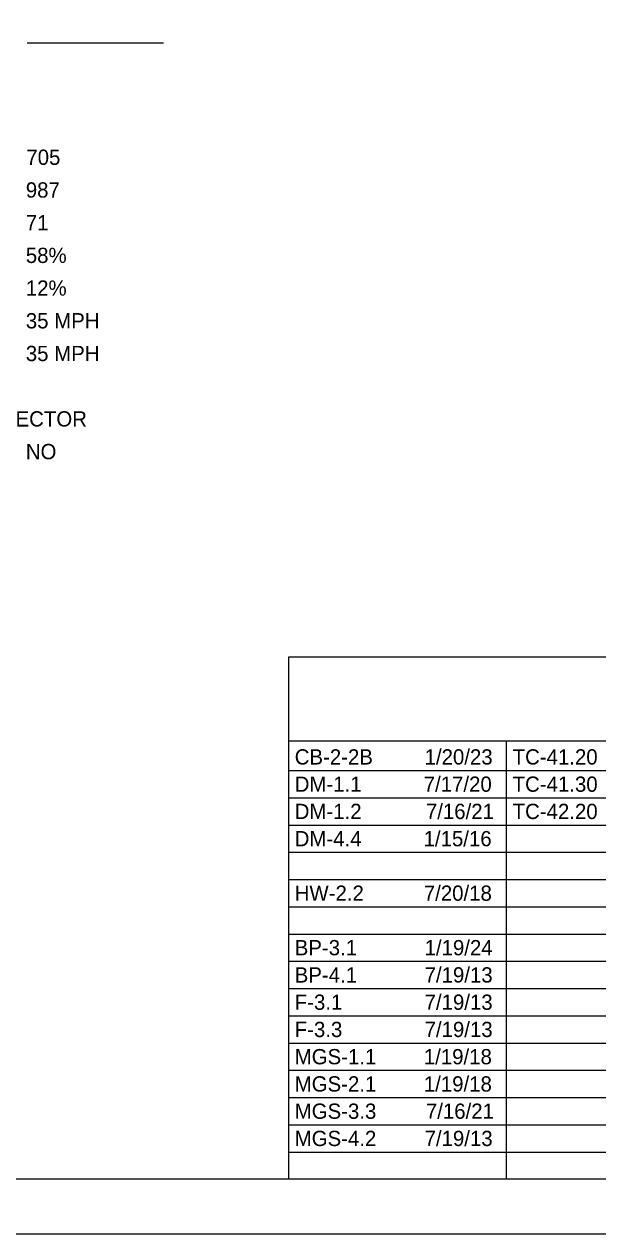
# Model space of a CAD drawing. Extents: x 0 to 34, y 0 to 22.
# Drawn here: x 7.72 to 12.99, y 0 to 11.1 of the extents above; entities that cross this region are included whole.
import ezdxf

# ---------------------------------------------------------------- set-up
doc = ezdxf.new("R2010")
doc.units = 0
for name, color, linetype in [('GM_X_County', 7, 'Continuous'), ('GM_X_Minor_Lake', 7, 'Continuous'), ('GM_X_Minor_Lake_Text', 7, 'Continuous'), ('GM_X_Minor_River_Text', 7, 'Continuous')]:
    doc.layers.add(name, color=color, linetype=linetype)

msp = doc.modelspace()

# ---------------------------------------------------------------- linework, layer by layer
at = {"layer": 'GM_X_County'}
msp.add_lwpolyline([(0, 0), (34, 0), (34, 22), (0, 22)], close=True, dxfattribs=at)
at = {"layer": 'GM_X_Minor_Lake_Text'}
for p, q in [((9, 10.922), (7.75, 10.922)), ((10.15, 5.292), (23.6, 5.292)), ((10.15, 0.5), (10.15, 5.292)), ((10.15, 4.521), (23.6, 4.521)), ((12.15, 0.5), (12.15, 4.521)), ((10.15, 4.25), (23.6, 4.25)), ((10.15, 4), (23.6, 4)), ((10.15, 3.75), (23.6, 3.75)), ((10.15, 3.5), (23.6, 3.5)), ((10.15, 3.25), (23.6, 3.25)), ((10.15, 3), (23.6, 3)), ((10.15, 2.75), (23.6, 2.75)), ((10.15, 2.5), (23.6, 2.5)), ((10.15, 2.25), (23.6, 2.25)), ((10.15, 2), (23.6, 2)), ((10.15, 1.75), (23.6, 1.75)), ((10.15, 1.5), (23.6, 1.5)), ((10.15, 1.25), (23.6, 1.25)), ((10.15, 1), (23.6, 1)), ((10.15, 0.75), (23.6, 0.75))]:
    msp.add_line(p, q, dxfattribs=at)
at = {"layer": 'GM_X_Minor_River_Text'}
msp.add_lwpolyline([(1.5, 21.5), (33.5, 21.5), (33.5, 0.5), (1.5, 0.5)], close=True, dxfattribs=at)

# ---------------------------------------------------------------- texts
at = {"layer": 'GM_X_Minor_Lake'}
for s, p in [('705', (7.742, 9.806)), ('987', (7.737, 9.506)), ('71', (7.737, 9.206)), ('58%', (7.737, 8.906)), ('12%', (7.737, 8.606)), ('35 MPH', (7.737, 8.306)), ('35 MPH', (7.737, 8.006)), ('                                                                   (5) RURAL MAJOR COLLECTOR', (1.994, 7.406)), ('NO', (7.737, 7.106)), ('CB-2-2B', (10.205, 4.305)), ('1/20/23', (11.397, 4.305)), ('TC-41.20', (12.205, 4.305)), ('DM-1.1', (10.205, 4.055)), ('7/17/20', (11.389, 4.055)), ('TC-41.30', (12.205, 4.055)), ('DM-1.2', (10.205, 3.805)), ('7/16/21', (11.409, 3.805)), ('TC-42.20', (12.205, 3.805)), ('DM-4.4', (10.205, 3.555)), ('1/15/16', (11.388, 3.555)), ('HW-2.2', (10.205, 3.055)), ('7/20/18', (11.39, 3.055)), ('BP-3.1', (10.205, 2.555)), ('1/19/24', (11.397, 2.555)), ('BP-4.1', (10.205, 2.305)), ('7/19/13', (11.397, 2.305)), ('F-3.1', (10.205, 2.055)), ('7/19/13', (11.397, 2.055)), ('F-3.3', (10.205, 1.805)), ('7/19/13', (11.397, 1.805)), ('MGS-1.1', (10.205, 1.555)), ('1/19/18', (11.39, 1.555)), ('MGS-2.1', (10.205, 1.305)), ('1/19/18', (11.39, 1.305)), ('MGS-3.3', (10.205, 1.055)), ('7/16/21', (11.409, 1.055)), ('MGS-4.2', (10.205, 0.805)), ('7/19/13', (11.397, 0.805))]:
    msp.add_text(s, height=0.14, dxfattribs=at).set_placement(p)

doc.saveas('drawing.dxf')
